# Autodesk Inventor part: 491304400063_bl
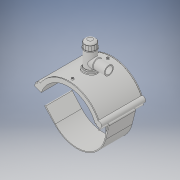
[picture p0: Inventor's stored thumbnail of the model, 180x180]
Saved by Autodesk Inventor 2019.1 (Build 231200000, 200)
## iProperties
Created: 2017-07
Part Number: 491304400063_bl
Material: Generic
Description: PLASSON TAPPING TEE SADDLE 400mm x 63mm
Document SubType Name: Modeling
Designer: KIM
Mass: 1712.7 g
Surface Area: 2671.49 cm^2
Volume: 1712.7 cm^3
Density: 1 g/cm^3
Appearance: Default
Author: KIM
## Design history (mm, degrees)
derived "491304.ipt"
feature "Solid1::491304.ipt" dims "ScaleForDerivedMember" = 10
feature "Solid2::491304.ipt" dims "ScaleForDerivedMember" = 10
feature "Solid4::491304.ipt" dims "ScaleForDerivedMember" = 10
feature "Solid5::491304.ipt" dims "ScaleForDerivedMember" = 10
tag "TaggingFeature1"
body "Solid1"
body "Solid2"
other parameters: "d1" = 101.118 [user parameter], "d4" = 306 [user parameter], "d5" = 0 [user parameter], "d6" = 0.1 [user parameter], "d8" = 0 [user parameter], "d41" = 97.65 [user parameter], "d43" = 0 [user parameter], "d45" = 0 [user parameter], "d47" = 234.159 [user parameter], "d78" = 235 [user parameter], "d79" = 15 [user parameter], "d80" = 122.4 [user parameter], "d82" = 5 deg [user parameter], "d84" = 4 [user parameter], "d85" = 14 [user parameter], "d86" = 0 [user parameter], "d87" = 3 [user parameter], "d88" = 0 [user parameter], "d97" = 6.12 [user parameter], "d98" = 0 [user parameter], "d102" = 4 [user parameter], "d120" = 140 deg [user parameter], "d123" = 606.708 [user parameter], "d126" = 0 [user parameter], "d153" = 306 [user parameter], "d154" = 0 [user parameter], "d159" = -59.7764 [user parameter], "d162" = 183.6 [user parameter], "d163" = 0 [user parameter], "d169" = 4.0905 [user parameter], "d172" = 0 [user parameter], "d173" = 1 [user parameter], "d176" = 20 deg [user parameter], "d177" = 28 [user parameter], "d180" = 0 [user parameter], "d184" = 22.4 [user parameter], "d188" = 15 [user parameter], "d189" = 28 [user parameter], "d190" = 0 [user parameter], "d195" = 90 deg [user parameter], "d197" = 0 [user parameter], "d199" = 0 [user parameter], "d200" = 28 [user parameter], "d202" = 0 [user parameter], "d203" = 208 [user parameter], "d206" = 75.6 [user parameter], "d207" = 156 [user parameter], "d208" = 162.24 [user parameter], "d209" = 193.44 [user parameter], "d210" = 76.86 [user parameter], "d212" = 72.45 [user parameter], "d213" = 48.15 [user parameter], "d216" = 0 [user parameter], "d219" = 4 [user parameter], "d224" = 0 [user parameter], "d259" = 50.4 [user parameter], "d260" = 63 [user parameter], "d265" = 0 [user parameter], "d267" = 13.00006 [user parameter], "d268" = 2.60001 [user parameter], "d269" = 2.60001 [user parameter], "d271" = 2.60001 [user parameter], "d273" = 0 [user parameter], "d274" = 23.56194 [user parameter], "d280" = 0 [user parameter], "d283" = 0 [user parameter], "d285" = 0 [user parameter], "d294" = 206 [user parameter], "d299" = 85 [user parameter], "d300" = 3 [user parameter], "d301" = 5 [user parameter], "d303" = 81.9 [user parameter], "d304" = 69.3 [user parameter], "d305" = 45 deg [user parameter], "d306" = 50.4 [user parameter], "d310" = 1 [user parameter], "L" = 306 [user parameter], "d_t" = 6 [user parameter], "H2" = 208 [user parameter], "H1" = 85 [user parameter], "d_1" = 63 [user parameter]
